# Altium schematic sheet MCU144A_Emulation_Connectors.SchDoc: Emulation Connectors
size 431 x 279 mm; DrawnBy: Gustavo Martinez; SheetNumber: 7; SheetTotal: 8
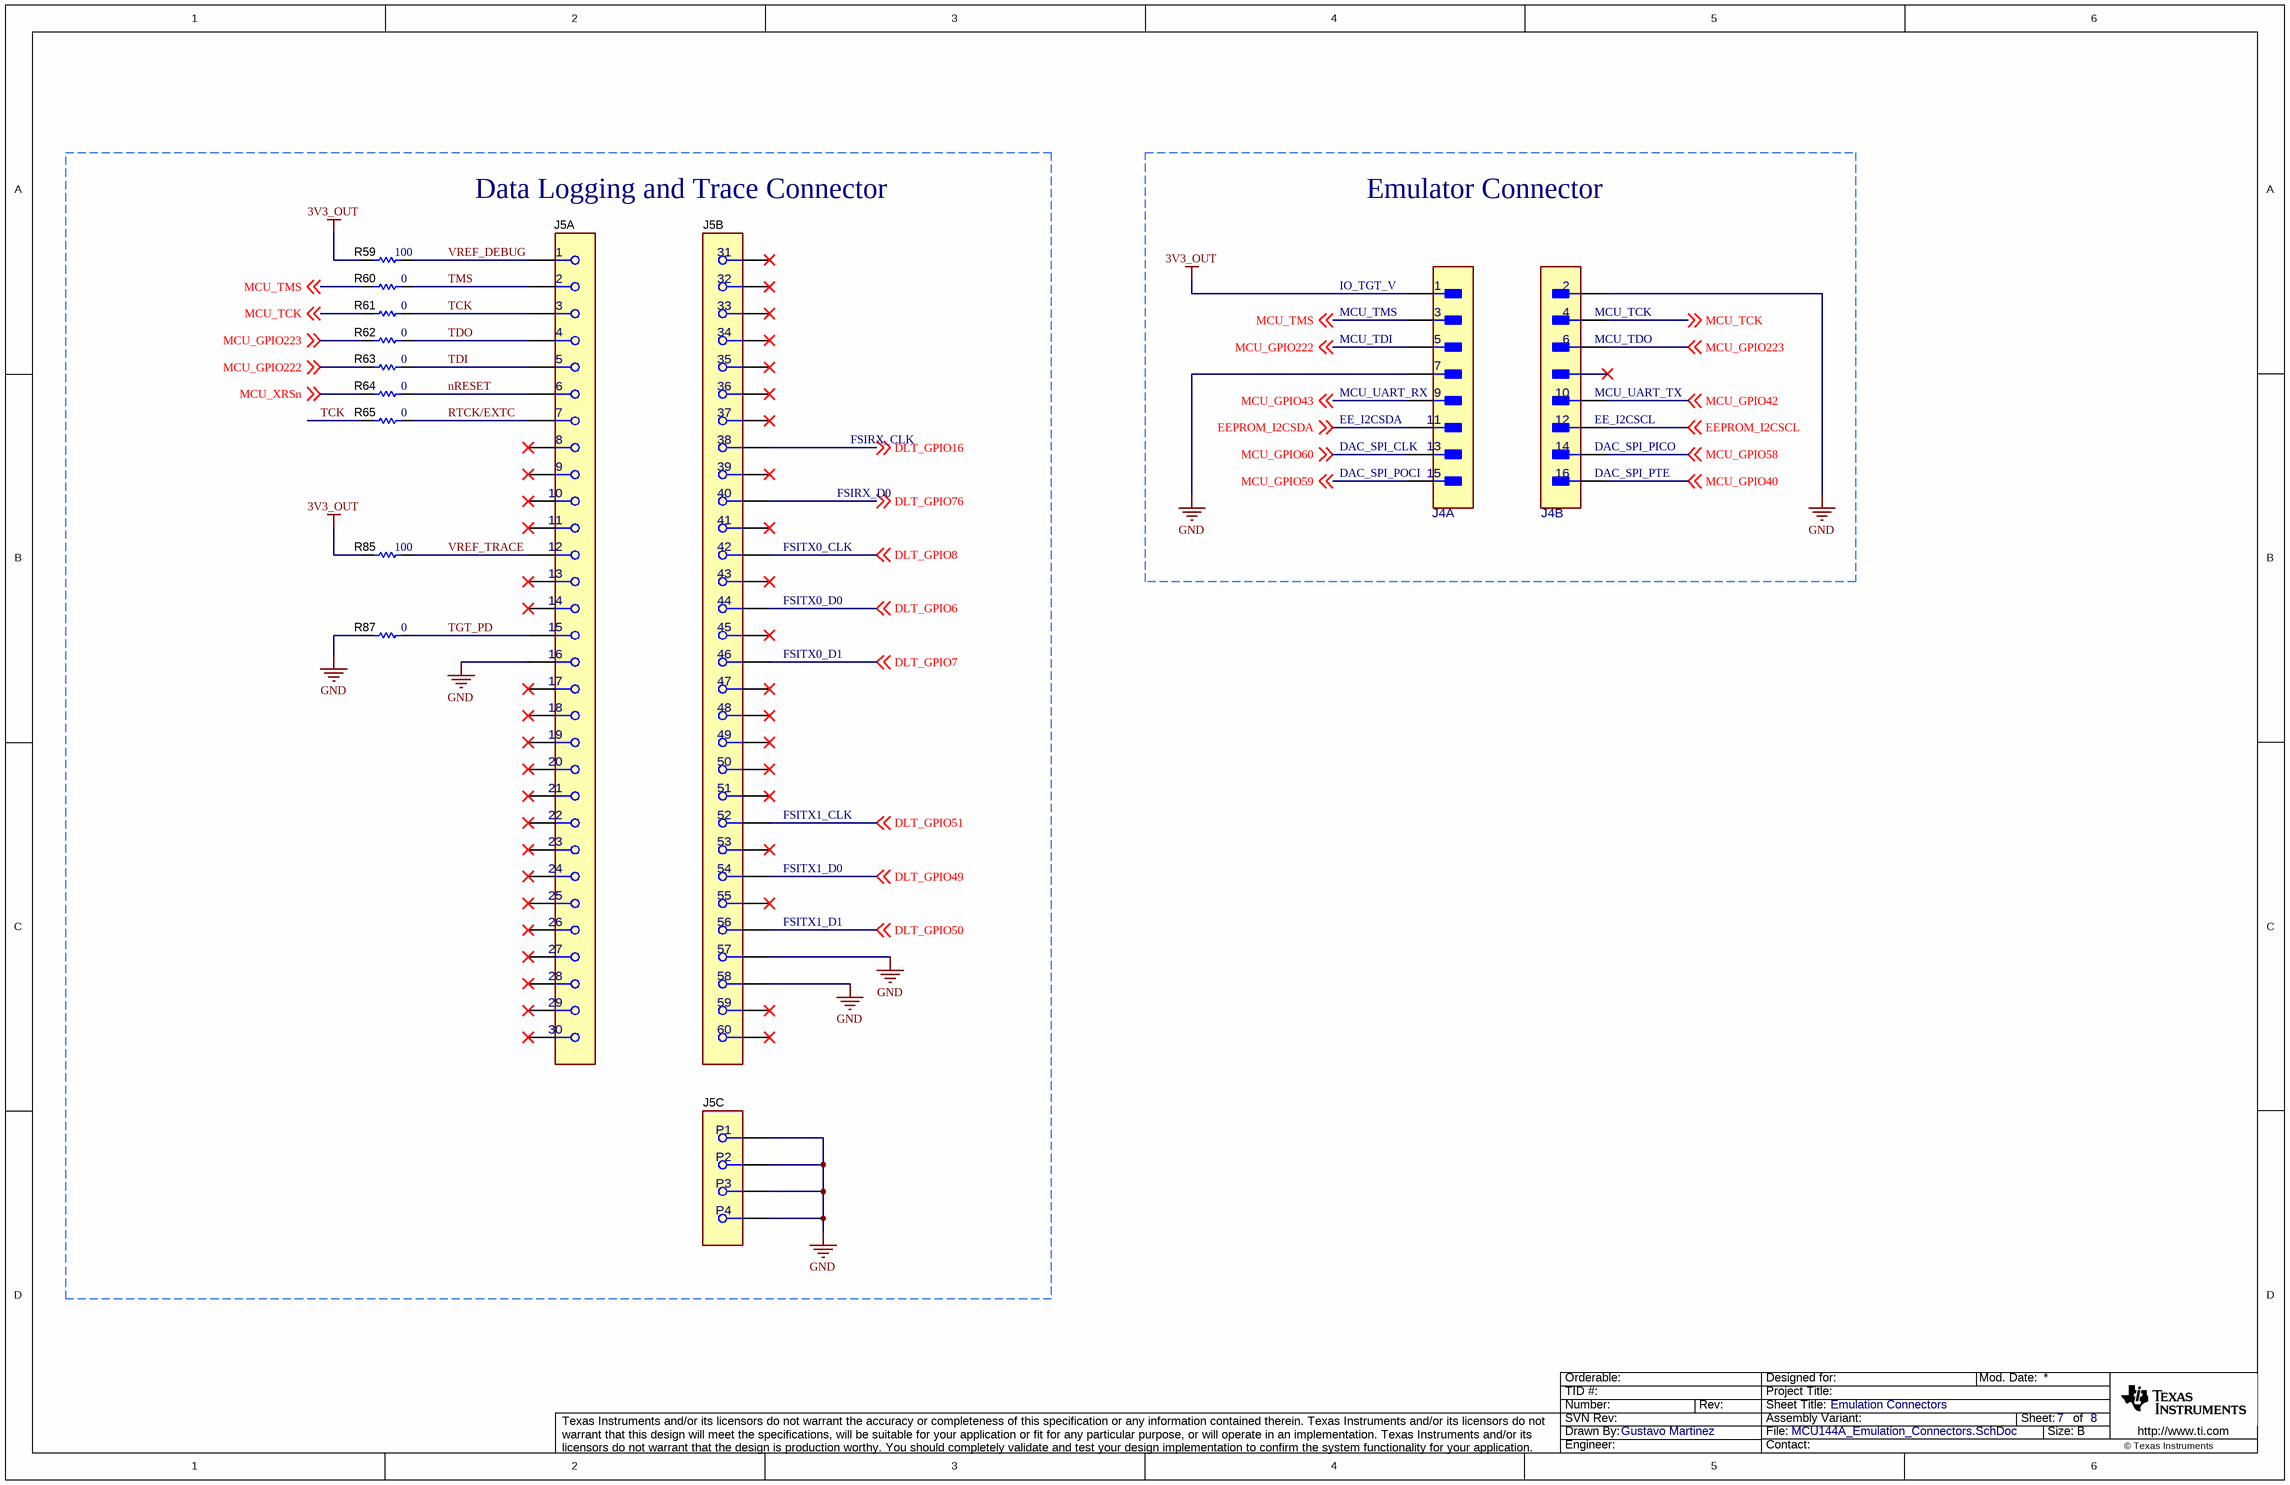
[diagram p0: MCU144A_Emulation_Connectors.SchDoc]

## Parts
J4  TSM-108-01-L-DV-008-P-TR  [FP-TSM-108-01-L-DV-008-P-TR_HDR15-MFG]  (value not drawn)  (parts A,B of 2)
J5  QSH-030-01-L-D-A  [FP-QSH-030-01-L-D-A_CONN_60-MFG]  (value not drawn)  (parts A,B,C of 3)
R59  ValueDisplayed: 100  [0402]  (hidden comment: CRCW0402100RFKED)
R60  ValueDisplayed: 0  [0402]  (hidden comment: CRCW04020000Z0ED)
R61  ValueDisplayed: 0  [0402]  (hidden comment: CRCW04020000Z0ED)
R62  ValueDisplayed: 0  [0402]  (hidden comment: CRCW04020000Z0ED)
R63  ValueDisplayed: 0  [0402]  (hidden comment: CRCW04020000Z0ED)
R64  ValueDisplayed: 0  [0402]  (hidden comment: CRCW04020000Z0ED)
R65  ValueDisplayed: 0  [0402]  (hidden comment: CRCW04020000Z0ED)
R85  ValueDisplayed: 100  [0402]  (hidden comment: CRCW0402100RFKED)
R87  ValueDisplayed: 0  [0402]  (hidden comment: CRCW04020000Z0ED)

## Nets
3V3_OUT: J4.1 R59.1 R85.1
GND: J4.2 J4.7 J5.16 J5.57 J5.58 J5.P1 J5.P2 J5.P3 J5.P4 R87.1
DLT_GPIO6: J5.44 ; off-sheet DLT_GPIO6
DLT_GPIO7: J5.46 ; off-sheet DLT_GPIO7
DLT_GPIO8: J5.42 ; off-sheet DLT_GPIO8
DLT_GPIO16: J5.38 ; off-sheet DLT_GPIO16
DLT_GPIO49: J5.54 ; off-sheet DLT_GPIO49
DLT_GPIO50: J5.56 ; off-sheet DLT_GPIO50
DLT_GPIO51: J5.52 ; off-sheet DLT_GPIO51
DLT_GPIO76: J5.40 ; off-sheet DLT_GPIO76
EEPROM_I2CSCL: J4.12 ; off-sheet EEPROM_I2CSCL
EEPROM_I2CSDA: J4.11 ; off-sheet EEPROM_I2CSDA
MCU_GPIO40: J4.16 ; off-sheet MCU_GPIO40
MCU_GPIO42: J4.10 ; off-sheet MCU_GPIO42
MCU_GPIO43: J4.9 ; off-sheet MCU_GPIO43
MCU_GPIO58: J4.14 ; off-sheet MCU_GPIO58
MCU_GPIO59: J4.15 ; off-sheet MCU_GPIO59
MCU_GPIO60: J4.13 ; off-sheet MCU_GPIO60
MCU_GPIO222: J4.5 R63.1 ; off-sheet MCU_GPIO222
MCU_GPIO223: J4.6 R62.1 ; off-sheet MCU_GPIO223
MCU_TCK: J4.4 R61.1 ; off-sheet MCU_TCK
MCU_TMS: J4.3 R60.1 ; off-sheet MCU_TMS
MCU_XRSn: R64.1 ; off-sheet MCU_XRSn
nRESET: J5.6 R64.2
RTCK/EXTC: J5.7 R65.2
TCK: J5.3 R61.2 R65.1
TDI: J5.5 R63.2
TDO: J5.4 R62.2
TGT_PD: J5.15 R87.2
TMS: J5.2 R60.2
VREF_DEBUG: J5.1 R59.2
VREF_TRACE: J5.12 R85.2

Not connected (* = marked no-connect by the designer): J5 8* 9* 10* 11* 13* 14* 17* 18* 19* 20* 21* 22* 23* 24* 25* 26* 27* 28* 29* 30* 31* 32* 33* 34* 35* 36* 37* 39* 41* 43* 45* 47* 48* 49* 50* 51* 53* 55* 59* 60*

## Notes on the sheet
- Data Logging and Trace Connector
- Emulator Connector
- (near J4) IO_TGT_V
- (near J4) MCU_TDI
- (near J4) MCU_TMS
- (near J4) MCU_TCK
- (near J4) MCU_TDO
- (near J4) MCU_UART_RX
- (near J4) EE_I2CSDA
- (near J4) EE_I2CSCL
- (near J4) MCU_UART_TX
- (near J5) FSIRX_D0
- (near J5) FSIRX_CLK
- (near J4) DAC_SPI_POCI
- (near J4) DAC_SPI_CLK
- (near J4) DAC_SPI_PICO
- (near J4) DAC_SPI_PTE
- (near J5) FSITX0_CLK
- (near J5) FSITX0_D0
- (near J5) FSITX0_D1
- (near J5) FSITX1_CLK
- (near J5) FSITX1_D0
- (near J5) FSITX1_D1

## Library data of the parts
J4 = CMP-0121706-1: Conn Unshrouded HDR 16 POS 2.54mm Solder ST SMT; Manufacturer: Samtec; ContactFinish: Gold,Nickel; Row_Count: 2; AEC Qualified: No; Conn Gender: Male; Conn Orientation: Vertical; SizeZ_mm: 10.16mm; Standoff Height: 1.02mm
J5 = CMP-0088387-1: CONN RCPT HI-SPD .5MM 60POS DL; Manufacturer: Samtec; Voltage_V: 175V; AEC Qualified: No; Current_A: 25A; DUT-Pitch_mm: 0.5mm; Standoff Height: 0.407mm; Row_Count: 2; Conn Gender: Female; SizeZ_mm: 3.327mm; ContactFinish: Gold,Nickel; Conn Orientation: Vertical; Is Female: yes
R59 R85 = CMP-0025951-3: RES, 100, 1%, 0.063 W, AEC-Q200 Grade 0, 0402; Manufacturer: Vishay-Dale; Power_W: 63mW; TempCo: 100 ppm/C; Value_Code: 100R; Value: 100; EIA_Code: E96; SizeX_mm: 1; SizeY_mm: 0.5; SizeZ_mm: 0.6; Value2: 0.063W; AEC Qualified: Y; VDC_V: 50V; AEC Category: Q200; AEC Grade: 0
R60-R65 R87 = CMP-0026822-3: RES, 0, 5%, 0.063 W, AEC-Q200 Grade 0, 0402; Manufacturer: Vishay-Dale; Power_W: 63mW; TempCo: 200 ppm/C; Value_Code: 0000; Value: 0; EIA_Code: E24; SizeX_mm: 1; SizeY_mm: 0.5; SizeZ_mm: 0.6; Value2: 0.063W; AEC Qualified: Y; AEC Category: Q200; VDC_V: 50V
